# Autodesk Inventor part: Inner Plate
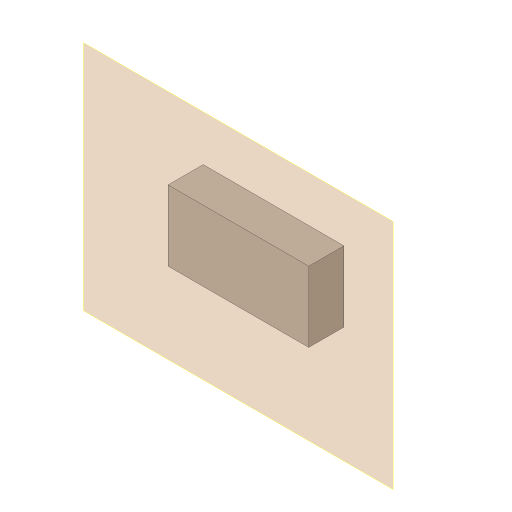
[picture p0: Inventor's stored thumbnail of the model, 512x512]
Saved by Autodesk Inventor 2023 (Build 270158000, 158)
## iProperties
Created: 2017-06
Part Number: Inner Plate
Material: Generic
Document SubType Name: Modeling
Designer: CADCIM 00
Density: 1 g/cm^3
Appearance: Default
Author: CADCIM 00
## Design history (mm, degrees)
workplane "Work Plane1"
sketch "Sketch1"
  geometry: L1 (-20, 10)-(20, 10); L2 (20, 10)-(20, -10); L3 (20, -10)-(-20, -10); L4 (-20, -10)-(-20, 10); 1 further point
  constraints: 8 end point, 2 parallel, 1 horizontal, 1 perpendicular
workplane "Work Plane2"
extrude "Extrusion1" new body sketch "Sketch1" stored distance "d0" = 25.4; taper "d1" = 0 deg
body "Solid1"
